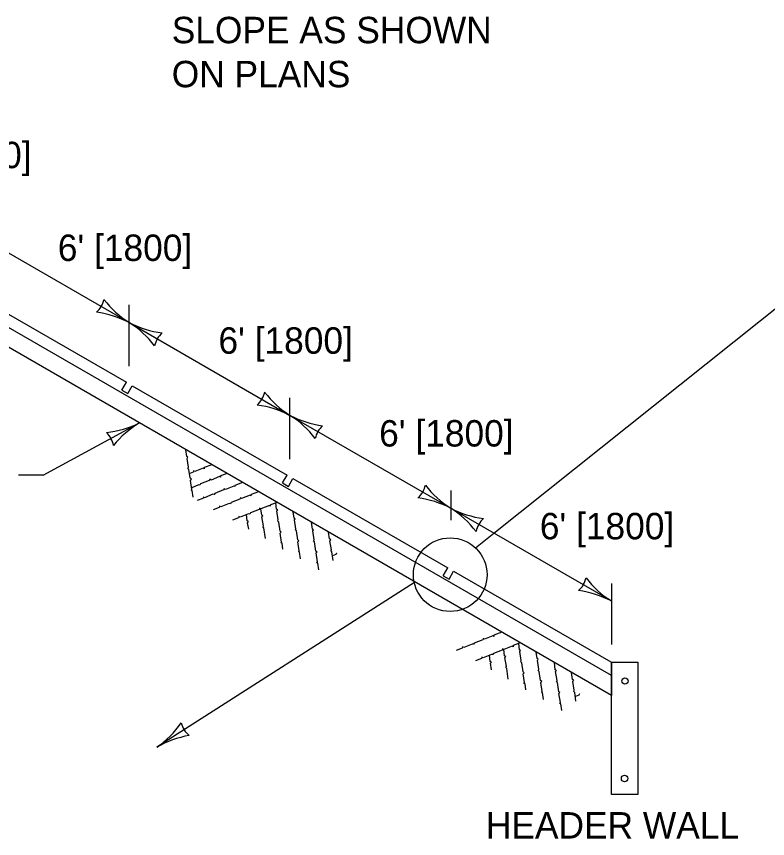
# Model space of a CAD drawing. Extents: x 49991.4 to 50021, y 49987.6 to 50011.4.
# Drawn here: x 50010.46 to 50012.166, y 49990.678 to 49992.544 of the extents above; entities that cross this region are included whole.
import ezdxf

# ---------------------------------------------------------------- set-up
doc = ezdxf.new("R2010")
doc.units = 0
for name, color, linetype in [('Level 1', 7, 'Continuous'), ('Level 2', 7, 'Continuous'), ('Level 3', 7, 'Continuous')]:
    doc.layers.add(name, color=color, linetype=linetype)

msp = doc.modelspace()

# ---------------------------------------------------------------- linework, layer by layer
at = {"layer": 'Level 1'}
for p, q in [((50011.8116, 49991.0475), (50009.8357, 49992.1883)), ((50011.8116, 49991.0024), (50009.8357, 49992.1432)), ((50010.3586, 49991.9164), (50010.71, 49991.7138)), ((50010.6997, 49991.6956), (50010.71, 49991.7138)), ((50010.7131, 49991.6878), (50010.7235, 49991.7058)), ((50010.7235, 49991.7058), (50011.075, 49991.503)), ((50010.6997, 49991.6956), (50010.7131, 49991.6878)), ((50011.0646, 49991.485), (50011.075, 49991.503)), ((50011.0646, 49991.485), (50011.0781, 49991.4772)), ((50011.0781, 49991.4772), (50011.0884, 49991.4951)), ((50011.0884, 49991.4951), (50011.44, 49991.2924)), ((50011.4295, 49991.2742), (50011.44, 49991.2924)), ((50011.4295, 49991.2742), (50011.4429, 49991.2665)), ((50011.4429, 49991.2665), (50011.4534, 49991.2845)), ((50011.4534, 49991.2845), (50011.8048, 49991.0817)), ((50011.8048, 49991.0817), (50011.8116, 49991.0779)), ((50011.8116, 49991.0779), (50011.8116, 49991.0475)), ((50011.8116, 49991.0779), (50011.8715, 49991.0779)), ((50011.8116, 49990.7775), (50011.8116, 49991.0779)), ((50011.8715, 49991.0779), (50011.8715, 49990.7775)), ((50011.8116, 49991.0475), (50011.8116, 49991.0025)), ((50011.8715, 49990.7775), (50011.8116, 49990.7775))]:
    msp.add_line(p, q, dxfattribs=at)
for points in [[(50010.855, 49991.4964), (50010.8523, 49991.5159), (50010.85, 49991.5179), (50010.8512, 49991.5207), (50010.848, 49991.5409), (50010.8499, 49991.5434), (50010.8471, 49991.5451), (50010.845, 49991.5605)], [(50010.9042, 49991.5263), (50010.8868, 49991.52), (50010.8867, 49991.5174), (50010.8845, 49991.5186), (50010.8654, 49991.5108), (50010.8639, 49991.5117)], [(50010.8639, 49991.5117), (50010.8625, 49991.5126), (50010.8614, 49991.5096), (50010.854, 49991.5067)], [(50010.8616, 49991.4525), (50010.8596, 49991.4679), (50010.857, 49991.4688), (50010.8588, 49991.4704), (50010.8556, 49991.4909), (50010.8578, 49991.4933), (50010.8554, 49991.4951), (50010.855, 49991.4964)], [(50010.9387, 49991.5064), (50010.9238, 49991.5008), (50010.9237, 49991.4981), (50010.9215, 49991.4994), (50010.9024, 49991.4915), (50010.8996, 49991.4933), (50010.8984, 49991.4903), (50010.8788, 49991.4827), (50010.8772, 49991.4801), (50010.8742, 49991.4805), (50010.8586, 49991.4742)], [(50010.974, 49991.486), (50010.9563, 49991.4795), (50010.9561, 49991.4767), (50010.954, 49991.4779), (50010.9349, 49991.4703), (50010.932, 49991.4719), (50010.9308, 49991.469), (50010.9112, 49991.4613), (50010.9097, 49991.4587), (50010.9067, 49991.4593), (50010.8878, 49991.4514), (50010.885, 49991.4527), (50010.884, 49991.4499), (50010.8705, 49991.4448)], [(50011.0103, 49991.465), (50010.9932, 49991.4587), (50010.993, 49991.4559), (50010.9909, 49991.4571), (50010.9717, 49991.4495), (50010.969, 49991.4511), (50010.9678, 49991.4483), (50010.9481, 49991.4405), (50010.9466, 49991.4379), (50010.9436, 49991.4384), (50010.9247, 49991.4306), (50010.9219, 49991.432), (50010.9208, 49991.4291), (50010.9075, 49991.4239)], [(50011.0522, 49991.4408), (50011.0371, 49991.4352), (50011.037, 49991.4326), (50011.0348, 49991.4338), (50011.0156, 49991.426), (50011.0128, 49991.4277), (50011.0116, 49991.4248), (50010.992, 49991.4172), (50010.9904, 49991.4145), (50010.9875, 49991.415), (50010.9684, 49991.4073), (50010.9657, 49991.4086), (50010.9647, 49991.4055), (50010.9513, 49991.4005)], [(50011.0259, 49991.3592), (50011.0224, 49991.3828), (50011.0202, 49991.3849), (50011.0214, 49991.3876), (50011.018, 49991.4078), (50011.02, 49991.4103), (50011.0174, 49991.412), (50011.0154, 49991.4259)], [(50011.0655, 49991.3347), (50011.0637, 49991.3482), (50011.0611, 49991.3491), (50011.0627, 49991.3509), (50011.0596, 49991.3712), (50011.0618, 49991.3736), (50011.0593, 49991.3754), (50011.0563, 49991.3963), (50011.054, 49991.3983), (50011.0552, 49991.4011), (50011.0519, 49991.4214), (50011.0539, 49991.4238), (50011.0513, 49991.4254), (50011.0493, 49991.4397)], [(50010.9879, 49991.3802), (50010.9855, 49991.3946), (50010.9875, 49991.3971), (50010.9848, 49991.3988), (50010.9828, 49991.4132)], [(50011.1057, 49991.3126), (50011.1036, 49991.3282), (50011.1011, 49991.3291), (50011.1026, 49991.3309), (50011.0994, 49991.3512), (50011.1018, 49991.3536), (50011.0992, 49991.3555), (50011.0963, 49991.3763), (50011.094, 49991.3784), (50011.0952, 49991.3811), (50011.0919, 49991.4015), (50011.0938, 49991.4038), (50011.0912, 49991.4054), (50011.0892, 49991.4195)], [(50011.1471, 49991.2874), (50011.145, 49991.3029), (50011.1424, 49991.3038), (50011.144, 49991.3057), (50011.1409, 49991.326), (50011.1432, 49991.3284), (50011.1406, 49991.3302), (50011.1376, 49991.351), (50011.1353, 49991.3531), (50011.1365, 49991.3558), (50011.1332, 49991.3762), (50011.1352, 49991.3785), (50011.1326, 49991.3801), (50011.1304, 49991.3957)], [(50011.1796, 49991.3092), (50011.1768, 49991.3286), (50011.1745, 49991.3306), (50011.1758, 49991.3335), (50011.1725, 49991.3536), (50011.1744, 49991.356), (50011.1717, 49991.3578), (50011.1695, 49991.3731)], [(50011.1884, 49991.3243), (50011.1871, 49991.3252), (50011.1859, 49991.3223), (50011.1785, 49991.3195)], [(50011.563, 49991.1459), (50011.5449, 49991.1394), (50011.5448, 49991.1365), (50011.5427, 49991.138), (50011.5235, 49991.1302), (50011.5207, 49991.1318), (50011.5195, 49991.1289), (50011.4999, 49991.1214), (50011.4984, 49991.1187), (50011.4954, 49991.1192), (50011.4765, 49991.1114), (50011.4736, 49991.1128), (50011.4727, 49991.1097), (50011.4592, 49991.1046)], [(50011.6047, 49991.1219), (50011.5889, 49991.1158), (50011.5887, 49991.1132), (50011.5866, 49991.1144), (50011.5674, 49991.1067), (50011.5645, 49991.1084), (50011.5633, 49991.1055), (50011.5438, 49991.0978), (50011.5423, 49991.0952), (50011.5392, 49991.0957), (50011.5203, 49991.0879), (50011.5174, 49991.0892), (50011.5165, 49991.0864), (50011.5031, 49991.0813)], [(50011.5776, 49991.0398), (50011.5741, 49991.0635), (50011.5721, 49991.0656), (50011.5731, 49991.0684), (50011.5699, 49991.0887), (50011.5717, 49991.0911), (50011.5691, 49991.0926), (50011.5672, 49991.1067)], [(50011.6173, 49991.0153), (50011.6155, 49991.0291), (50011.6128, 49991.0297), (50011.6145, 49991.0316), (50011.6113, 49991.0518), (50011.6136, 49991.0542), (50011.6111, 49991.0561), (50011.608, 49991.0769), (50011.6058, 49991.0791), (50011.6069, 49991.0819), (50011.6037, 49991.1021), (50011.6056, 49991.1045), (50011.603, 49991.1061), (50011.6011, 49991.1205)], [(50011.5397, 49991.061), (50011.5373, 49991.0754), (50011.5394, 49991.0778), (50011.5365, 49991.0794), (50011.5347, 49991.0938)], [(50011.6574, 49990.9933), (50011.6553, 49991.009), (50011.6527, 49991.0098), (50011.6545, 49991.0116), (50011.6513, 49991.0319), (50011.6536, 49991.0343), (50011.651, 49991.0361), (50011.648, 49991.057), (50011.6457, 49991.059), (50011.647, 49991.062), (50011.6437, 49991.0821), (50011.6455, 49991.0845), (50011.6429, 49991.0862), (50011.6409, 49991.101)], [(50011.6988, 49990.968), (50011.6968, 49990.9836), (50011.6941, 49990.9845), (50011.6958, 49990.9863), (50011.6926, 49991.0066), (50011.6949, 49991.009), (50011.6924, 49991.0108), (50011.6894, 49991.0317), (50011.6871, 49991.0337), (50011.6883, 49991.0365), (50011.685, 49991.0568), (50011.687, 49991.0592), (50011.6843, 49991.0608), (50011.6821, 49991.0772)], [(50011.7313, 49990.9898), (50011.7286, 49991.0093), (50011.7263, 49991.0114), (50011.7275, 49991.0141), (50011.7242, 49991.0343), (50011.7262, 49991.0368), (50011.7235, 49991.0384), (50011.7212, 49991.0546)], [(50011.7403, 49991.0051), (50011.7389, 49991.0058), (50011.7376, 49991.003), (50011.7302, 49991.0002)]]:
    msp.add_lwpolyline(points, dxfattribs=at)
for centre in [(50011.8426, 49991.0353), (50011.8417, 49990.8138), (50011.8417, 49990.8138)]:
    msp.add_circle(centre, 0.0073, dxfattribs=at)
at = {"layer": 'Level 3'}
for p, q in [((50011.5449, 49991.371), (50012.4953, 49992.1298)), ((50010.3518, 49992.0598), (50010.7167, 49991.8491)), ((50010.7167, 49991.7499), (50010.7167, 49991.8891)), ((50010.7167, 49991.8491), (50011.0816, 49991.6385)), ((50011.0816, 49991.5392), (50011.0816, 49991.6785)), ((50011.0816, 49991.6385), (50011.4467, 49991.4276)), ((50010.521, 49991.5024), (50010.7397, 49991.6213)), ((50010.521, 49991.5024), (50010.4647, 49991.5024)), ((50011.4467, 49991.4676), (50011.4467, 49991.4003)), ((50011.4467, 49991.4276), (50011.8116, 49991.217)), ((50011.5032, 49991.3374), (50011.5449, 49991.371)), ((50011.3648, 49991.2586), (50010.7795, 49990.8849)), ((50011.8116, 49991.257), (50011.8116, 49991.1179))]:
    msp.add_line(p, q, dxfattribs=at)
msp.add_circle((50011.4456, 49991.2767), 0.0836, dxfattribs=at)
for centre, radius, start, end in [((50010.6057, 49991.9132), 0.0548, 312.1418, 347.8642), ((50010.8357, 49992.0369), 0.2223, 217.459, 237.6425), ((50010.6104, 49991.6418), 0.233, 62.8303, 82.0802), ((50010.5977, 49991.6613), 0.2223, 37.4522, 57.6358), ((50010.8232, 49992.0564), 0.233, 242.8235, 262.0734), ((50010.8278, 49991.785), 0.0548, 132.1351, 167.8574), ((50010.9706, 49991.7026), 0.0548, 312.1351, 347.8574), ((50011.2006, 49991.8262), 0.2223, 217.4522, 237.6358), ((50010.9752, 49991.4312), 0.233, 62.8235, 82.0734), ((50010.9626, 49991.4507), 0.2223, 37.4522, 57.6358), ((50011.188, 49991.8457), 0.233, 242.8235, 262.0734), ((50010.6416, 49991.8208), 0.2223, 275.9875, 296.171), ((50010.8609, 49991.4223), 0.233, 121.3588, 140.6086), ((50011.1926, 49991.5743), 0.0548, 132.1351, 167.8574), ((50010.627, 49991.56), 0.0548, 10.6703, 46.3927), ((50011.3357, 49991.4918), 0.0548, 312.1351, 347.8574), ((50011.5657, 49991.6154), 0.2223, 217.4522, 237.6358), ((50011.3403, 49991.2204), 0.233, 62.8235, 82.0734), ((50011.3278, 49991.2398), 0.2223, 37.4708, 57.6543), ((50011.553, 49991.6349), 0.233, 242.8421, 262.0919), ((50011.5578, 49991.3636), 0.0548, 132.1536, 167.8759), ((50011.7005, 49991.2811), 0.0548, 312.1536, 347.8759), ((50011.9305, 49991.4048), 0.2223, 217.4708, 237.6543), ((50011.7053, 49991.0097), 0.233, 62.8421, 82.0919), ((50010.6445, 49991.0748), 0.233, 305.3929, 324.6427), ((50010.8875, 49990.9539), 0.0548, 194.7044, 230.4268), ((50010.8913, 49990.6927), 0.2223, 100.0216, 120.2051)]:
    msp.add_arc(centre, radius, start, end, dxfattribs=at)

# ---------------------------------------------------------------- texts
at = {"layer": 'Level 2'}
for s, p in [('SLOPE AS SHOWN', (50010.8131, 49992.4835)), ('ON PLANS', (50010.8131, 49992.3835)), ("6' [1800]", (50010.1894, 49992.1998)), ("6' [1800]", (50010.5543, 49991.9891)), ("6' [1800]", (50010.9192, 49991.7784)), ("6' [1800]", (50011.2842, 49991.5677)), ("6' [1800]", (50011.6491, 49991.357)), ('HEADER WALL', (50011.5266, 49990.6775))]:
    msp.add_text(s, height=0.06, dxfattribs=at).set_placement(p)

doc.saveas('drawing.dxf')
